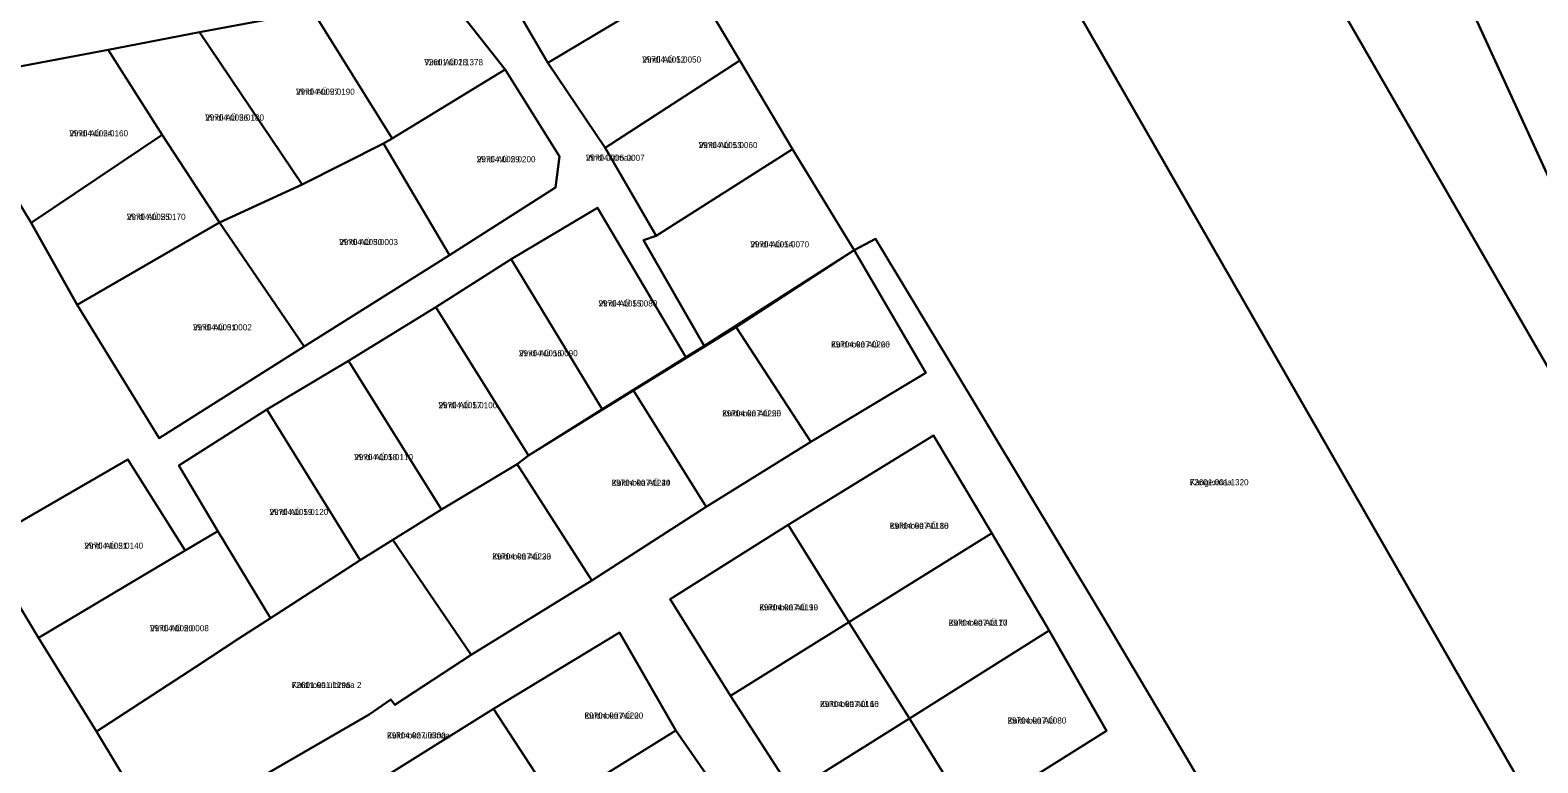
# Model space of a CAD drawing. Extents: x 504287 to 537970, y 6539941 to 6586214.
# Drawn here: x 516534.2 to 516906.1, y 6563756.4 to 6563937.1 of the extents above; entities that cross this region are included whole.
import ezdxf

# ---------------------------------------------------------------- set-up
doc = ezdxf.new("R2010")
doc.units = 0
for name, color, linetype in [('L_AADRESS', 7, 'Continuous'), ('PIIR', 7, 'Continuous'), ('TUNNUS', 7, 'Continuous')]:
    doc.layers.add(name, color=color, linetype=linetype)

msp = doc.modelspace()

# ---------------------------------------------------------------- linework, layer by layer
at = {"layer": 'PIIR'}
for points in [[(516707.02, 6564609.45), (516708.65, 6564604.72), (517022.98, 6563694.64), (517006.77, 6563683.7), (516931.71, 6563850.61), (516927.81, 6563859.28), (516612.58, 6564546.64), (516599.87, 6564591.06), (516634.95, 6564593.53), (516656.69, 6564586.65)], [(516492.75, 6564575.34), (516528.64, 6564593.13), (516556.22, 6564603.01), (516571.83, 6564602.67), (516599.87, 6564591.06), (516612.58, 6564546.64), (516927.81, 6563859.28), (516931.71, 6563850.61), (517006.77, 6563683.7)], [(516744.27, 6564025.8), (516982.09, 6563611.59), (516927.25, 6563577.2), (516835.52, 6563730.64), (516822.58, 6563752.44), (516814.57, 6563765.92), (516798.6, 6563792.96), (516760.66, 6563855.96), (516742.75, 6563885.64), (516737.52, 6563882.87), (516722.3, 6563907.76), (516709.28, 6563929.6), (516697.15, 6563950.09), (516684.83, 6563970.67), (516672.52, 6563991.27), (516658.45, 6564008.29), (516673.61, 6564011.42), (516744.15, 6564026.01)], [(516684.83, 6563970.67), (516697.15, 6563950.09), (516661.89, 6563929.04), (516649.81, 6563949.8)], [(516661.89, 6563929.04), (516697.15, 6563950.09), (516709.28, 6563929.6), (516676.05, 6563908.09)], [(516513.22, 6563924.64), (516534.48, 6563889.54), (516545.82, 6563869.35), (516566.07, 6563836.49), (516601.85, 6563859.06), (516637.63, 6563881.62), (516663.8, 6563898.32), (516664.83, 6563905.95), (516651.4, 6563927.39), (516636.37, 6563946.49), (516603.97, 6563941.74), (516576.02, 6563936.6), (516553.47, 6563932.24)], [(516623.56, 6563910.38), (516603.97, 6563941.74), (516636.37, 6563946.49), (516651.4, 6563927.39)], [(516603.97, 6563941.74), (516623.56, 6563910.38), (516621.41, 6563909.14), (516601.36, 6563899.01), (516576.02, 6563936.6)], [(516553.47, 6563932.24), (516576.02, 6563936.6), (516601.36, 6563899.01), (516580.95, 6563889.66), (516566.78, 6563911.27)], [(516553.47, 6563932.24), (516566.78, 6563911.27), (516534.48, 6563889.54), (516513.22, 6563924.64)], [(516621.41, 6563909.14), (516623.56, 6563910.38), (516651.4, 6563927.39), (516664.83, 6563905.95), (516663.8, 6563898.32), (516637.63, 6563881.62)], [(516676.05, 6563908.09), (516709.28, 6563929.6), (516722.3, 6563907.76), (516688.65, 6563886.39)], [(516534.48, 6563889.54), (516566.78, 6563911.27), (516580.95, 6563889.66), (516545.82, 6563869.35)], [(516621.41, 6563909.14), (516637.63, 6563881.62), (516601.85, 6563859.06), (516580.95, 6563889.66), (516601.36, 6563899.01)], [(516685.55, 6563885.34), (516688.65, 6563886.39), (516722.3, 6563907.76), (516737.52, 6563882.87), (516700.49, 6563859.27)], [(516674.16, 6563893.25), (516695.99, 6563856.47), (516675.31, 6563843.62), (516652.85, 6563880.62)], [(516580.95, 6563889.66), (516601.85, 6563859.06), (516566.07, 6563836.49), (516545.82, 6563869.35)], [(516708.38, 6563863.86), (516737.52, 6563882.87), (516755.19, 6563852.63), (516726.79, 6563835.57)], [(516652.85, 6563880.62), (516675.31, 6563843.62), (516657.15, 6563832.22), (516634.3, 6563868.75)], [(516612.76, 6563855.54), (516634.3, 6563868.75), (516657.15, 6563832.22), (516654.32, 6563830.06), (516635.69, 6563818.86)], [(516683.06, 6563848.27), (516708.38, 6563863.86), (516726.79, 6563835.57), (516700.98, 6563819.52)], [(516612.76, 6563855.54), (516635.69, 6563818.86), (516623.67, 6563811.4), (516615.66, 6563806.42), (516592.64, 6563843.57)], [(516654.32, 6563830.06), (516657.15, 6563832.22), (516683.06, 6563848.27), (516700.98, 6563819.52), (516672.74, 6563801.42)], [(516580.52, 6563813.58), (516570.87, 6563829.78), (516592.64, 6563843.57), (516615.66, 6563806.42), (516593.53, 6563792.11)], [(516722.29, 6563749.26), (516735.69, 6563726.63), (516766.07, 6563743.18), (516799.74, 6563764.29), (516785.62, 6563789.05), (516771.4, 6563813.09), (516757.06, 6563837.14), (516721.19, 6563815.1), (516692.06, 6563796.82), (516706.99, 6563772.95)], [(516721.19, 6563815.1), (516757.06, 6563837.14), (516771.4, 6563813.09), (516736.13, 6563791.14)], [(516522.28, 6563810.4), (516558.32, 6563831.23), (516572.5, 6563808.75), (516536.31, 6563787.22)], [(516654.32, 6563830.06), (516672.74, 6563801.42), (516643.03, 6563783.07), (516623.67, 6563811.4), (516635.69, 6563818.86)], [(516692.06, 6563796.82), (516721.19, 6563815.1), (516736.13, 6563791.14), (516706.99, 6563772.95)], [(516536.31, 6563787.22), (516572.5, 6563808.75), (516580.52, 6563813.58), (516593.53, 6563792.11), (516585.67, 6563787.07), (516575.1, 6563780.13), (516550.62, 6563764.18)], [(516623.67, 6563811.4), (516643.03, 6563783.07), (516624.17, 6563770.73), (516623.2, 6563772.02), (516617.83, 6563768.33), (516591.67, 6563753.24), (516566.1, 6563738.35), (516550.62, 6563764.18), (516575.1, 6563780.13), (516585.67, 6563787.07), (516593.53, 6563792.11), (516615.66, 6563806.42)], [(516736.13, 6563791.14), (516771.4, 6563813.09), (516785.62, 6563789.05), (516751.12, 6563767.4)], [(516706.99, 6563772.95), (516736.13, 6563791.14), (516751.12, 6563767.4), (516722.29, 6563749.26)], [(516751.12, 6563767.4), (516785.62, 6563789.05), (516799.74, 6563764.29), (516766.07, 6563743.18)], [(516648.67, 6563704.2), (516664.67, 6563679.71), (516695.76, 6563699.65), (516724.03, 6563718.14), (516709.44, 6563741.49), (516693.5, 6563764.43), (516679.56, 6563788.61), (516648.53, 6563769.72), (516618.65, 6563751.1), (516633.73, 6563727.26)], [(516648.53, 6563769.72), (516679.56, 6563788.61), (516693.5, 6563764.43), (516663.97, 6563746.07)], [(516618.65, 6563751.1), (516648.53, 6563769.72), (516663.97, 6563746.07), (516633.73, 6563727.26)], [(516722.29, 6563749.26), (516751.12, 6563767.4), (516766.07, 6563743.18), (516735.69, 6563726.63)], [(516663.97, 6563746.07), (516693.5, 6563764.43), (516709.44, 6563741.49), (516679.91, 6563723.16)]]:
    msp.add_lwpolyline(points, close=True, dxfattribs=at)
for points in [[(517379.78, 6562919.5), (517180.26, 6563268.51), (517112.27, 6563384.86), (516982.09, 6563611.59), (516744.27, 6564025.8), (516744.15, 6564026.01), (516730.68, 6564049.47), (516444.24, 6564548.52), (516445.68, 6564549.17), (516449.01, 6564550.8), (516452.43, 6564551.99), (516458.23, 6564554.15), (516464.7, 6564557.42), (516469.05, 6564559.51), (516471.43, 6564560.88), (516474.52, 6564562.81), (516484.15, 6564569.31), (516486.47, 6564571.24), (516492.75, 6564575.34), (517006.77, 6563683.7), (517111.59, 6563503.08), (517311.3, 6563151.72)], [(516649.81, 6563949.8), (516661.89, 6563929.04), (516676.05, 6563908.09), (516688.65, 6563886.39), (516685.55, 6563885.34), (516700.49, 6563859.27), (516695.99, 6563856.47), (516674.16, 6563893.25), (516652.85, 6563880.62), (516634.3, 6563868.75), (516612.76, 6563855.54), (516592.64, 6563843.57), (516570.87, 6563829.78), (516580.52, 6563813.58), (516572.5, 6563808.75), (516558.32, 6563831.23), (516522.28, 6563810.4)], [(516591.67, 6563753.24), (516617.83, 6563768.33), (516623.2, 6563772.02), (516624.17, 6563770.73), (516643.03, 6563783.07), (516672.74, 6563801.42), (516700.98, 6563819.52), (516726.79, 6563835.57), (516755.19, 6563852.63), (516737.52, 6563882.87), (516742.75, 6563885.64), (516760.66, 6563855.96), (516798.6, 6563792.96), (516814.57, 6563765.92), (516822.58, 6563752.44)], [(516522.28, 6563810.4), (516536.31, 6563787.22), (516550.62, 6563764.18), (516566.1, 6563738.35), (516568.78, 6563733.94), (516584.22, 6563708.44), (516602.05, 6563679.44), (516618.72, 6563651.98), (516626.42, 6563639.26), (516643.89, 6563610.25), (516632.5, 6563603.12), (516615.95, 6563592.72), (516598.44, 6563581.96), (516580.99, 6563571.31), (516558.61, 6563557.61), (516550.89, 6563552.98), (516458.32, 6563497.36)]]:
    msp.add_lwpolyline(points, dxfattribs=at)

# ---------------------------------------------------------------- texts
at = {"layer": 'L_AADRESS'}
for s, p in [('Vindi AÜ 12', (516685.23, 6563929.09)), ('Vindi AÜ 28', (516631.43, 6563928.43)), ('Vindi AÜ 27', (516599.79, 6563921.16)), ('Vindi AÜ 26', (516577.41, 6563914.79)), ('Vindi AÜ 24', (516543.88, 6563910.89)), ('Vindi AÜ 13', (516699.13, 6563908)), ('Vindi AÜ 29', (516644.39, 6563904.51)), ('Vindi üldmaa', (516671.3, 6563904.88)), ('Vindi AÜ 25', (516558.07, 6563890.31)), ('Vindi AÜ 30', (516610.46, 6563884.1)), ('Vindi AÜ 14', (516711.86, 6563883.52)), ('Vindi AÜ 15', (516674.42, 6563868.95)), ('Vindi AÜ 31', (516574.4, 6563863.07)), ('Kuldnoka AÜ 26', (516731.79, 6563858.85)), ('Vindi AÜ 16', (516654.8, 6563856.68)), ('Vindi AÜ 17', (516634.95, 6563843.87)), ('Kuldnoka AÜ 25', (516704.93, 6563841.85)), ('Vindi AÜ 18', (516614.16, 6563831.06)), ('Kuldnoka AÜ 24', (516677.65, 6563824.74)), ('Kangermaa', (516820.27, 6563824.88)), ('Vindi AÜ 19', (516593.26, 6563817.55)), ('Kuldnoka AÜ 18', (516746.28, 6563814.14)), ('Vindi AÜ 21', (516547.6, 6563809.23)), ('Kuldnoka AÜ 23', (516648.2, 6563806.57)), ('Kuldnoka AÜ 19', (516714.07, 6563794.03)), ('Vindi AÜ 20', (516563.8, 6563788.88)), ('Kuldnoka AÜ 17', (516760.8, 6563790.24)), ('Kuldnoka üldmaa 2', (516598.77, 6563774.88)), ('Kuldnoka AÜ 16', (516729.06, 6563770.2)), ('Kuldnoka AÜ 20', (516670.95, 6563767.34)), ('Kuldnoka AÜ 8', (516775.31, 6563766.12)), ('Kuldnoka üldmaa', (516622.25, 6563762.45))]:
    msp.add_text(s, height=1.5, dxfattribs=at).set_placement(p)
at = {"layer": 'TUNNUS'}
for s, p in [('29704:005:0050', (516685.23, 6563929.09)), ('72601:001:1378', (516631.43, 6563928.43)), ('29704:005:0190', (516599.79, 6563921.16)), ('29704:005:0180', (516577.41, 6563914.79)), ('29704:005:0160', (516543.88, 6563910.89)), ('29704:005:0060', (516699.13, 6563908)), ('29704:005:0200', (516644.39, 6563904.51)), ('29704:005:0007', (516671.3, 6563904.88)), ('29704:005:0170', (516558.07, 6563890.31)), ('29704:005:0003', (516610.46, 6563884.1)), ('29704:005:0070', (516711.86, 6563883.52)), ('29704:005:0080', (516674.42, 6563868.95)), ('29704:005:0002', (516574.4, 6563863.07)), ('29704:007:0260', (516731.79, 6563858.85)), ('29704:005:0090', (516654.8, 6563856.68)), ('29704:005:0100', (516634.95, 6563843.87)), ('29704:007:0250', (516704.93, 6563841.85)), ('29704:005:0110', (516614.16, 6563831.06)), ('29704:007:0240', (516677.65, 6563824.74)), ('72601:001:1320', (516820.27, 6563824.88)), ('29704:005:0120', (516593.26, 6563817.55)), ('29704:007:0180', (516746.28, 6563814.14)), ('29704:005:0140', (516547.6, 6563809.23)), ('29704:007:0230', (516648.2, 6563806.57)), ('29704:007:0190', (516714.07, 6563794.03)), ('29704:005:0008', (516563.8, 6563788.88)), ('29704:007:0170', (516760.8, 6563790.24)), ('72601:001:1296', (516598.77, 6563774.88)), ('29704:007:0160', (516729.06, 6563770.2)), ('29704:007:0200', (516670.95, 6563767.34)), ('29704:007:0080', (516775.31, 6563766.12)), ('29704:007:0300', (516622.25, 6563762.45))]:
    msp.add_text(s, height=1.5, dxfattribs=at).set_placement(p)

doc.saveas('drawing.dxf')
